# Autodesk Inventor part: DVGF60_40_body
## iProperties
Created: 2010-04
Part Number: DVGF60_40_body
Document SubType Name: Modeling
Designer: TB
Mass: 688.638 g
Surface Area: 1349.83 cm^2
Volume: 688.638 cm^3
Density: 1 g/cm^3
Author: TB
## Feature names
1. Kropp [Revolution]
2. Chamfer
3. Extrusion2
4. Hole1
5. Revolution2
6. Hole2
7. Fillet1
8. Extrusion3
9. Hole3
